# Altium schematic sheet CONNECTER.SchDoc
size 420 x 297 mm
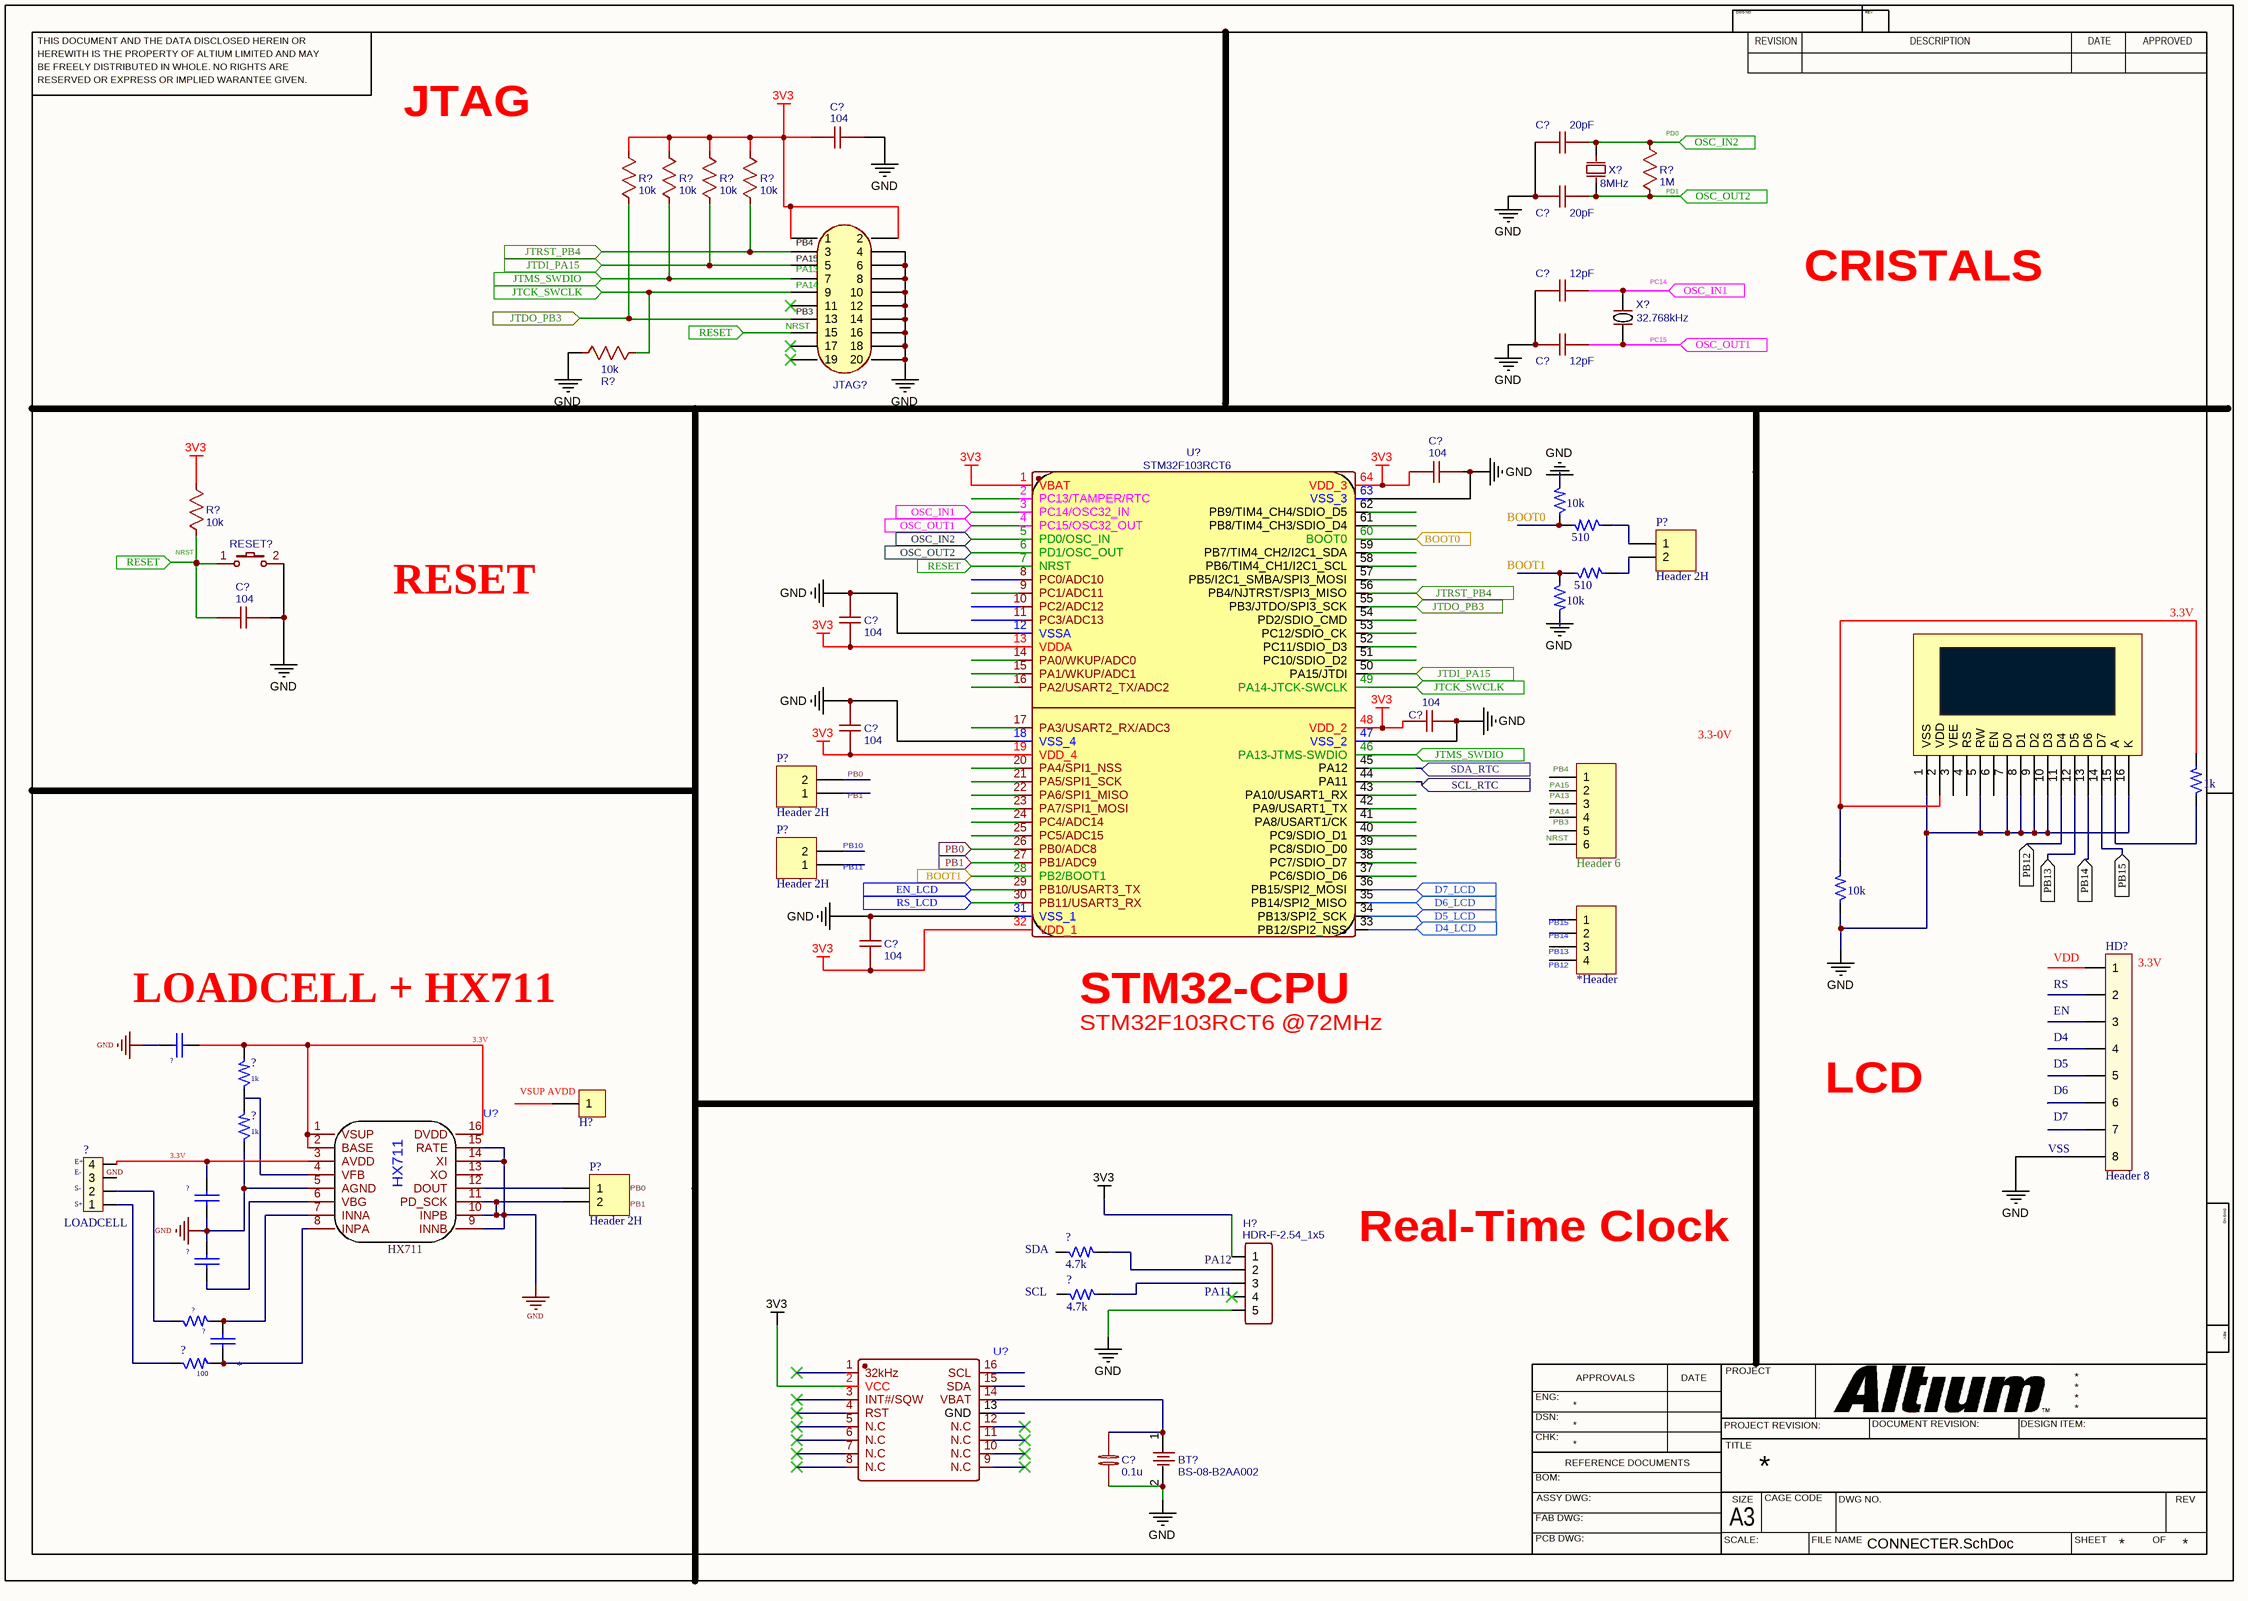
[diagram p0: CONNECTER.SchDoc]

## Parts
(Parts that share a designator on the sheet are numbered #1, #2 ... from top to bottom, then left to right.)
?#1  10k  [R1/6W]
?#2  510  [R1/6W]
?#3  510  [R1/6W]
?#4  10k  [R1/6W]
?#5  LCD  [LCD16X2]  (value not drawn)
?#6  Header 6  [HDR1X6]
?#7  1k  [R1/6W]
?#8  10k  [R1/6W]
?#9  *Header  [HDR1X4]
?#10  (no value)  [R1206]
?#11  1k  [R1/6W]
?#12  1k  [R1/6W]
?#13  (no value)  [R1206]
?#14  LOADCELL  [JP4]
?#15  4.7k  [R1/6W]
?#16  (no value)  [R1206]
?#17  4.7k  [R1/6W]
?#18  100  [R1/6W]
?#19  (no value)  [R1206]
?#20  (no value)  [R1/6W]
BT?  BS-08-B2AA002  [BAT-SMD_BS-08-B2AA001]
C?#1  104  [C0603]
C?#2  20pF  [C0603]
C?#3  20pF  [C0603]
C?#4  12pF  [C0603]
C?#5  12pF  [C0603]
C?#6  104  [C0603]
C?#7  104  [C0603]
C?#8  104  [C0603]
C?#9  104  [C0603]
C?#10  104  [C0603]
C?#11  104  [C0603]
C?#12  0.1u  [C0603]
H?#1  Header 1  [HEAD1]  (value not drawn)
H?#2  HDR-F-2.54_1x5  [HDR-F-2.54_1X5]
HD?  Header 8  [HED8V]
JTAG?  (no value)  [JTAG]
P?#1  Header 2H  [HDR1X2H]
P?#2  Header 2H  [HDR1X2H]
P?#3  Header 2H  [HDR1X2H]
P?#4  Header 2H  [HDR1X2H]
R?#1  1M  [R0603]
R?#2  10k  [R0603]
R?#3  10k  [R0603]
R?#4  10k  [R0603]
R?#5  10k  [R0603]
R?#6  10k  [R0603]
R?#7  10k  [R0603]
RESET?  K2-3.6×6.1_SMD  [KEY-SMD_L6.0-W3.5-LS8.0]  (value not drawn)
U?#1  STM32F103RCT6  [STM32F103RCT6]
U?#2  (no value)  [SOP-16_L10.0-W3.9-P1.27-LS6.0-BL]
U?#3  (no value)  [SOIC-16_L10.3-W7.5-P1.27-LS10.3-BL]
X?#1  8MHz  [HC-49SMD]
X?#2  32.768kHz  [CRYSTAL-TH_BD3.1-L8.0-P2.00-1]

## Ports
BOOT0 (in), BOOT1 (in), D4_LCD (in), D5_LCD (in), D6_LCD (in), D7_LCD (in), EN_LCD (in), JTCK_SWCLK (in), JTDI_PA15 (in), JTDO_PB3 (in), JTMS_SWDIO (in), JTRST_PB4 (in), OSC_IN1 (in), OSC_IN2 (in), OSC_OUT1 (in), OSC_OUT2 (in), PB0 (in), PB1 (in), PB12 (in), PB13 (in), PB14 (in), PB15 (in), RESET (in), RS_LCD (in), SCL_RTC (in), SDA_RTC (in)

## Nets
3V3: C?#1.1 C?#6.1 C?#8.1 C?#9.1 C?#10.1 C?#11.1 H?#2.1 JTAG?.1 JTAG?.2 R?#2.2 R?#3.2 R?#4.2 R?#5.2 R?#7.2 U?#1.1(VBAT) U?#1.13(VDDA) U?#1.19(VDD_4) U?#1.32(VDD_1) U?#1.48(VDD_2) U?#1.64(VDD_3) U?#3.2(VCC)
GND: ?#1.2 ?#4.2 ?#5.1(VSS) ?#5.5(RW) ?#5.7(D0) ?#5.8(D1) ?#5.9(D2) ?#5.10(D3) ?#5.16(K) ?#8.1 ?#10.1 ?#12.1 ?#13.2 ?#16.1 BT?.2 C?#1.2 C?#2.1 C?#3.1 C?#4.1 C?#5.1 C?#6.2 C?#7.2 C?#8.2 C?#9.2 C?#10.2 C?#11.2 C?#12.1 H?#2.5 HD?.8 JTAG?.4 JTAG?.6 JTAG?.8 JTAG?.10 JTAG?.12 JTAG?.14 JTAG?.16 JTAG?.18 JTAG?.20 P?#4.2 R?#6.1 RESET?.2 U?#1.12(VSSA) U?#1.18(VSS_4) U?#1.31(VSS_1) U?#1.47(VSS_2) U?#1.63(VSS_3) U?#2.5(AGND) U?#2.9(INNB) U?#2.10(INPB) U?#2.11(PD_SCK) U?#2.14(XI) U?#2.15(RATE)
BOOT0: U?#1.60(BOOT0) ; port BOOT0
BOOT1: U?#1.28(PB2/BOOT1) ; port BOOT1
D4_LCD: U?#1.33(PB12/SPI2_NSS) ; port D4_LCD
D5_LCD: U?#1.34(PB13/SPI2_SCK) ; port D5_LCD
D6_LCD: U?#1.35(PB14/SPI2_MISO) ; port D6_LCD
D7_LCD: U?#1.36(PB15/SPI2_MOSI) ; port D7_LCD
EN_LCD: U?#1.29(PB10/USART3_TX) ; port EN_LCD
JTCK_SWCLK: JTAG?.9 R?#6.2 U?#1.49(PA14-JTCK-SWCLK) ; port JTCK_SWCLK
JTDI_PA15: JTAG?.5 R?#4.1 U?#1.50(PA15/JTDI) ; port JTDI_PA15
JTDO_PB3: JTAG?.13 R?#2.1 U?#1.55(PB3/JTDO/SPI3_SCK) ; port JTDO_PB3
JTMS_SWDIO: JTAG?.7 R?#3.1 U?#1.46(PA13-JTMS-SWDIO) ; port JTMS_SWDIO
JTRST_PB4: JTAG?.3 R?#5.1 U?#1.56(PB4/NJTRST/SPI3_MISO) ; port JTRST_PB4
OSC_IN1: C?#4.2 U?#1.3(PC14/OSC32_IN) X?#2.2(OSC2) ; port OSC_IN1
OSC_IN2: C?#2.2 R?#1.2 U?#1.5(PD0/OSC_IN) X?#1.1(OSC1) ; port OSC_IN2
OSC_OUT1: C?#5.2 U?#1.4(PC15/OSC32_OUT) X?#2.1(OSC1) ; port OSC_OUT1
OSC_OUT2: C?#3.2 R?#1.1 U?#1.6(PD1/OSC_OUT) X?#1.2(OSC2) ; port OSC_OUT2
PB0: U?#1.26(PB0/ADC8) ; port PB0
PB1: U?#1.27(PB1/ADC9) ; port PB1
PB12: ?#5.11(D4) ; port PB12
PB13: ?#5.12(D5) ; port PB13
PB14: ?#5.13(D6) ; port PB14
PB15: ?#5.14(D7) ; port PB15
RESET: C?#7.1 JTAG?.15 R?#7.1 RESET?.1 U?#1.7(NRST) ; port RESET
RS_LCD: U?#1.30(PB11/USART3_RX) ; port RS_LCD
SCL_RTC: U?#1.44(PA11) ; port SCL_RTC
SDA_RTC: U?#1.45(PA12) ; port SDA_RTC
Net?#1_1: ?#1.1 ?#2.2
Net?#2_1: ?#2.1 P?#1.1
Net?#3_1: ?#3.1 ?#4.1
Net?#3_2: ?#3.2 P?#1.2
Net?#5_2: ?#5.2(VDD) ?#7.2 ?#8.2
Net?#5_15: ?#5.15(A) ?#7.1
Net?#10_2: ?#10.2 ?#11.2 U?#2.1(VSUP) U?#2.2(BASE) U?#2.16(DVDD)
Net?#12_2: ?#12.2 U?#2.4(VFB)
Net?#13_1: ?#13.1 ?#14.4 U?#2.3(AVDD)
Net?#14_1: ?#14.1 ?#20.1
Net?#14_2: ?#14.2 ?#18.1
Net?#15_2: ?#15.2 H?#2.2
Net?#16_2: ?#16.2 U?#2.6(VBG)
Net?#17_2: ?#17.2 H?#2.3
Net?#18_2: ?#18.2 ?#19.1 U?#2.7(INNA)
Net?#19_2: ?#19.2 ?#20.2 U?#2.8(INPA)
NetBT?_1: BT?.1 C?#12.2 U?#3.14(VBAT)
NetP?#4_1: P?#4.1 U?#2.12(DOUT)

Not connected (* = marked no-connect by the designer): ?#5 3(VEE) 4(RS) 6(EN); ?#6 1 2 3 4 5 6; ?#9 1 2 3 4; ?#11 1; ?#14 3; ?#15 1; ?#17 1; H?#1 1; H?#2 4*; HD? 1 2 3 4 5 6 7; JTAG? 11* 17* 19*; P?#2 1 2; P?#3 1 2; U?#1 2(PC13/TAMPER/RTC) 8(PC0/ADC10) 9(PC1/ADC11) 10(PC2/ADC12) 11(PC3/ADC13) 14(PA0/WKUP/ADC0) 15(PA1/WKUP/ADC1) 16(PA2/USART2_TX/ADC2) 17(PA3/USART2_RX/ADC3) 20(PA4/SPI1_NSS) 21(PA5/SPI1_SCK) 22(PA6/SPI1_MISO) 23(PA7/SPI1_MOSI) 24(PC4/ADC14) 25(PC5/ADC15) 37(PC6/SDIO_D6) 38(PC7/SDIO_D7) 39(PC8/SDIO_D0) 40(PC9/SDIO_D1) 41(PA8/USART1/CK) 42(PA9/USART1_TX) 43(PA10/USART1_RX) 51(PC10/SDIO_D2) 52(PC11/SDIO_D3) 53(PC12/SDIO_CK) 54(PD2/SDIO_CMD) 57(PB5/I2C1_SMBA/SPI3_MOSI) 58(PB6/TIM4_CH1/I2C1_SCL) 59(PB7/TIM4_CH2/I2C1_SDA) 61(PB8/TIM4_CH3/SDIO_D4) 62(PB9/TIM4_CH4/SDIO_D5); U?#2 13(XO); U?#3 1(32kHz)* 3(INT#/SQW)* 4(RST)* 5(N.C)* 6(N.C)* 7(N.C)* 8(N.C)* 9(N.C)* 10(N.C)* 11(N.C)* 12(N.C)* 13(GND) 15(SDA) 16(SCL)

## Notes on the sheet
- JTAG
- (near R?#1) PD1
- (near R?#1) PD0
- (near JTAG?) PB4
- (near JTAG?) PA15
- (near JTAG?) NRST
- (near JTAG?) PA13
- (near JTAG?) PA14
- (near JTAG?) PB3
- (near X?#2) PC14
- CRISTALS
- (near X?#2) PC15
- PC14
- PC15
- BOOT0
- (near R?#7) NRST
- BOOT1
- RESET
- 3.3V
- PB0
- PB1
- PB4
- PA15
- PA13
- 3.3-0V
- (near P?#3) PB10
- (near P?#3) PB11
- PA14
- PB3
- NRST
- PB15
- PB12
- PB13
- PB14
- (near HD?) RS
- (near HD?) VDD
- (near HD?) 3.3V
- (near ?#10) LOADCELL + HX711
- (near U?#1) STM32-CPU
- STM32F103RCT6 @72MHz
- (near HD?) EN
- (near HD?) D5
- (near HD?) D4
- (near H?#1) VSUP AVDD
- LCD
- (near HD?) D6
- (near HD?) D7
- (near ?#14) E+
- (near ?#14) E-
- (near ?#14) S-
- (near ?#14) S+
- (near ?#14) GND
- (near ?#13) 3.3V
- (near P?#4) PB0
- (near P?#4) PB1
- (near HD?) VSS
- (near U?#2) HX711
- (near ?#15) SDA
- (near H?#2) PA12
- Real-Time Clock
- (near ?#17) SCL
- (near H?#2) PA11

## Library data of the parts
?#1-?#4 ?#7 ?#8 ?#11 ?#12 ?#15 ?#17 ?#18 ?#20 = Res: Resistor 1/4W; Value: R1/4W - 1K
?#5 = LCD: Value: LCD16x2
?#6 = Header 6: Header, 6-Pin
?#9 = Header 4: Header, 4-Pin, Right Angle
?#10 ?#13 ?#16 ?#19 = CAP: Capacitor
?#14 = JP4: JP4 PIN
BT? = BS-08-B2AA002: Manufacturer: MYOUNG(美阳); Contributor: LCSC
C?#1 C?#6-C?#11 = 104: nameAlias: Value(F); Contributor: LCEDA_Lib
C?#2 C?#3 = 20pF: BOM_Manufacturer: FH; BOM_Manufacturer Part: 0603CG200J500NT; nameAlias: Capacitance
C?#4 C?#5 = 12pF: BOM_Manufacturer: FH; BOM_Manufacturer Part: 0603CG200J500NT; nameAlias: Capacitance
C?#12 = 0.1u: nameAlias: Value(F); Contributor: LCEDA_Lib
H?#1 = Header 1: Header, 1-Pin, Right Angle; Revised: Zion Blue
H?#2 = HDR-F-2.54_1x5: Contributor: LCEDA_Lib
HD? = Header 8: Header 8 Vit Broad
JTAG? = Header 10X2
P?#1-P?#4 = Header 2H: Header, 2-Pin, Right Angle
R?#1 = 1M: nameAlias: Value(Ω); Contributor: LCEDA_Lib
R?#2-R?#7 = 10k: nameAlias: Value(Ω); Contributor: LCEDA_Lib
RESET? = K2-3.6×6.1_SMD: BOM_Manufacturer Part: K2-1107ST-A4SW-06; Contributor: LCEDA_Lib; 制造商: 韩国韩荣
U?#1 = STM32F103RCT6: BOM_Manufacturer: ST(意法半导体); Contributor: wegi1
U?#2 = HX711
U?#3 = DS3231S#T&amp;R
X?#1 = 8MHz: BOM_Manufacturer: TAE; BOM_Manufacturer Part: HC-49SM8MHz20pF30ppm; nameAlias: Frequency; Contributor: T. Ruiz
X?#2 = 32.768kHz: BOM_Manufacturer: HD(浩都频率); BOM_Manufacturer Part: 7Q032768NW2; Contributor: LCSC; nameAlias: Frequency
